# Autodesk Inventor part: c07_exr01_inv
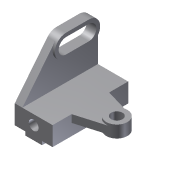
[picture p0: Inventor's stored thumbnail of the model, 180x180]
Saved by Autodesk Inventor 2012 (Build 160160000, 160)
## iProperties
Shininess: 77.0
Length Units: 11269
Angle Units: 11279
Time Units: 11290
Mass Units: 11283
Length Display Precision: 3
Angle Display Precision: 2
Created: 2001-12
Part Number: c07_exr01_inv
Document SubType Name: Modeling
Density: 1 g/cm^3
Material: Default
Density: 0.0
Volumn: 0.0
Area: 0.0
PropertySet Name: Model Information
Control State: 0
Master: False
Checked Out: False
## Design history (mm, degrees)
node "Sketch1"
sketch "Sketch2"
  geometry: L1 (26.807, 16.772)-(26.807, -8.428); L2 (26.807, -8.428)-(12.807, -8.428); L3 (12.807, -8.428)-(12.807, -13.228); L4 (12.807, -13.228)-(-9.193, -13.228); L5 (-9.193, -13.228)-(-9.193, -8.428); L6 (-9.193, -8.428)-(-23.193, -8.428); L7 (-23.193, -8.428)-(-23.193, 16.772); L8 (-23.193, 16.772)-(26.807, 16.772); C1 r 6.5 at (1.807, 4.172)
  constraints: 16 end point, 5 parallel, 2 equal length, 1 centre point, 1 collinear, 1 perpendicular, 1 vertical
  dimensions: "d0" = 50 distance of L7.end L1.start; "d1" = 22 distance of L3.end L4.end; "d2" = 30 distance between parallel lines of L8 L4; "d3" = 4.8 distance of L2.end L3.end; "d4" = 13 diameter of C1
extrude "Extrusion1" new body sketch "Sketch2" stored distance "d5" = 100; taper "d6" = 0 deg
sketch "Sketch3"
  geometry: L1 (25.2, 0)-(25.2, 100) reference; L2 (25.2, 0)-(79.543, 43.265); L3 (85.2, 55)-(85.2, 85); L4 (70.2, 100)-(25.2, 100); A1 r 15 centre (70.2, 55) between (79.543, 43.265) and (85.2, 55); A2 r 15 centre (70.2, 85) between (85.2, 85) and (70.2, 100)
  constraints: 6 end point, 4 point on circle, 4 tangent, 2 centre point, 1 equal radius, 1 parallel, 1 perpendicular
  dimensions: "d7" = 15 radius of A1; "d8" = 30 distance of L3.start L3.end; "d9" = 45 distance from line of L1 A2.centre
extrude "Extrusion2" join sketch "Sketch3" distance "d10" = 10; taper "d11" = 0 deg
sketch "Sketch4"
  geometry: L1 (-85.2, 55)-(-85.2, 85); L2 (-85.2, 85)-(-85.2, 55); L3 (-85.2, 55)-(-85.2, 85) reference; A1 r 15 centre (-70.2, 85) between (-85.2, 85) and (-85.2, 85); A2 r 15 centre (-70.2, 55) between (-85.2, 55) and (-85.2, 55); A3 r 15 centre (-70.2, 85) between (-70.2, 100) and (-85.2, 85) reference; A4 r 15 centre (-70.2, 55) between (-85.2, 55) and (-79.543, 43.265) reference
  constraints: 4 end point, 4 point on circle, 3 concentric, 3 tangent, 2 centre point, 2 collinear, 1 vertical
extrude "Extrusion3" join sketch "Sketch4" distance "d12" = 3; taper "d13" = 0 deg
sketch "Sketch5"
  geometry: L1 (-80.2, 55)-(-80.2, 85); L2 (-60.2, 85)-(-60.2, 55); A1 r 10 centre (-70.2, 55) between (-80.2, 55) and (-60.2, 55); A2 r 10 centre (-70.2, 85) between (-60.2, 85) and (-80.2, 85)
  constraints: 4 end point, 4 point on circle, 2 centre point
  dimensions: "d14" = 10 radius of A2
extrude "Extrusion4" cut sketch "Sketch5" stored distance "d15" = 3; taper "d16" = 0 deg
sketch "Sketch6"
  geometry: L1 (0, 25.146)-(38.94, 36.566); L2 (38.94, 63.434)-(0, 74.854); L3 (0, 74.854)-(0, 25.146); L4 (0, 100)-(0, 0) reference; L5 (0, 100)-(-40, 100) reference; A1 r 14 centre (35, 50) between (38.94, 36.566) and (38.94, 63.434)
  constraints: 6 end point, 2 point on circle, 2 tangent, 1 centre point, 1 collinear, 1 equal length, 1 vertical
  dimensions: "d17" = 14 radius of A1; "d18" = 35 distance from line of L4 A1.centre; "d19" = 50 distance from line of L5 A1.centre
extrude "Extrusion5" join sketch "Sketch6" distance "d20" = 10; taper "d21" = 0 deg
workplane "Work Plane1"
sketch "Sketch7"
  geometry: C1 r 14 at (75, 50); A1 r 14 centre (75, 50) between (78.94, 36.566) and (78.94, 63.434) reference
  constraints: 2 concentric, 1 centre point
extrude "Extrusion6" join sketch "Sketch7" stored distance "d23" = 16; taper "d24" = 0 deg
sketch "Sketch8"
  geometry: C1 r 14 at (0, 0) reference
hole "Hole1" sketch "Sketch8" at (0, 0) diameter "d25" = 15; stored, may be unused: countersink angle "d29" = 82 deg, drill point angle "d31" = 118 deg; dims "d26" = 6, "d27" = 4, "d28" = 2, "d30" = 8
body "Solid1"
other parameters: "d22" = -5
